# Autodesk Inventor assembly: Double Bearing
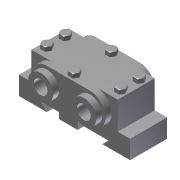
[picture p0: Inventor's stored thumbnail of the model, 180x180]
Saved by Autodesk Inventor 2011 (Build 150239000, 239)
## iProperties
Shininess: 64.0
Length Units: 11269
Angle Units: 11279
Time Units: 11290
Mass Units: 11283
Length Display Precision: 3
Angle Display Precision: 2
Created: 2002-02
Part Number: Double Bearing
Document SubType Name: Assembly
Designer: ***
Density: 0.0
Volumn: 0.0
Area: 0.0
PropertySet Name: Model Information
Control State: 0
Master: False
Checked Out: False
Author: ***
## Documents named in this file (5)
- C:\Users\CADSoft\Desktop\inventor\c12-inv-2010-prt\c12\Double Bearing\Double Bearing.iam
- C:\Users\CADSoft\Desktop\inventor\c12-inv-2010-prt\c12\Double Bearing\Base.ipt
- C:\Users\CADSoft\Desktop\inventor\c12-inv-2010-prt\c12\Double Bearing\Cap.ipt
- C:\Users\CADSoft\Desktop\inventor\c12-inv-2010-prt\c12\Double Bearing\Bushing.ipt
- C:\Users\CADSoft\Desktop\inventor\c12-inv-2010-prt\c12\Double Bearing\Bolt.ipt
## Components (10 placed, 4 different names)
1. Base:1 — Insert:1, Insert:2
2. Cap:1 — Insert:1, Insert:2, Insert:3, Insert:4, Insert:5, Insert:6
3. Bushing:1 — Insert:3
4. Bushing:2 — Insert:4
5. Bolt:1 — Insert:5
6. Bolt:6
7. Bolt:7
8. Bolt:8
9. Bolt:5 — Insert:6
10. Bolt:9
## Component patterns: Component Pattern 1 (4 elements), Component Pattern 2 (2 elements)
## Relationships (6: Insert 6)
- Insert:1: Base:1 ↔ Cap:1
- Insert:2: Base:1 ↔ Cap:1
- Insert:3: Cap:1 ↔ Bushing:1
- Insert:4: Cap:1 ↔ Bushing:2
- Insert:5: Cap:1 ↔ Bolt:1
- Insert:6: Cap:1 ↔ Bolt:5
